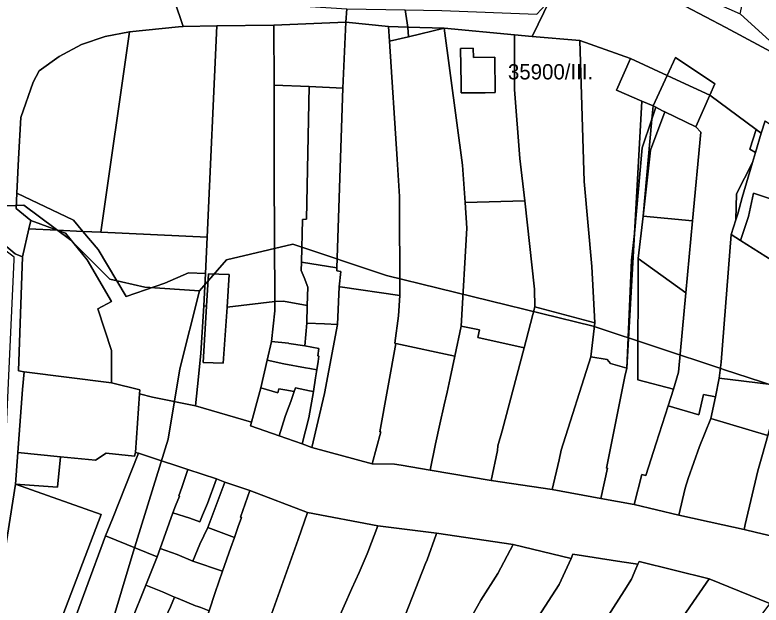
# Model space of a CAD drawing. Extents: x -545779 to -541342, y -1153413 to -1149956.
# Drawn here: x -544310.9 to -544066.7, y -1151258.7 to -1151065.6 of the extents above; entities that cross this region are included whole.
import ezdxf

# ---------------------------------------------------------------- set-up
doc = ezdxf.new("R2010")
doc.units = 0
for name, color, linetype in [('95590013', 7, 'Continuous'), ('95610013', 7, 'Continuous'), ('95630013', 7, 'Continuous'), ('95640013', 7, 'Continuous'), ('95660013', 7, 'Continuous')]:
    doc.layers.add(name, color=color, linetype=linetype)

msp = doc.modelspace()

# ---------------------------------------------------------------- linework, layer by layer
at = {"layer": '95590013'}
for points in [[(-544247.96, -1151138.3), (-544282.81, -1151136.71), (-544273.39, -1151071.2), (-544257.32, -1151069.5), (-544255.79, -1151069.46), (-544244.82, -1151069.16)], [(-544248.5, -1151150.2), (-544247.96, -1151138.3), (-544244.82, -1151069.16), (-544226.12, -1151068.98), (-544225.98, -1151088.64), (-544226, -1151117.83), (-544225.77, -1151159.43), (-544241.45, -1151161.21), (-544240.72, -1151150.55), (-544247.51, -1151150.33), (-544248.17, -1151160.9), (-544249.01, -1151160.82)], [(-544226.12, -1151068.98), (-544202.6, -1151068.01), (-544203.54, -1151089.61), (-544214.55, -1151089.05), (-544225.98, -1151088.64)], [(-544205.48, -1151148.34), (-544203.54, -1151089.61), (-544202.6, -1151068.01), (-544188.57, -1151069.43), (-544188.26, -1151074.21), (-544185.77, -1151112.81), (-544184.98, -1151125.02), (-544184.95, -1151157.48), (-544204.47, -1151154.62), (-544204.78, -1151154.62), (-544204.22, -1151149.61), (-544205.51, -1151149.34)], [(-544182.27, -1151069.63), (-544182.08, -1151072.75), (-544188.26, -1151074.21), (-544188.57, -1151069.43)], [(-544163.55, -1151126.98), (-544162.97, -1151135.38), (-544164.79, -1151167.47), (-544166.88, -1151177.25), (-544186.24, -1151173.11), (-544186.52, -1151173.06), (-544185.3, -1151164.08), (-544184.95, -1151157.48), (-544184.98, -1151125.02), (-544185.77, -1151112.81), (-544188.26, -1151074.21), (-544182.08, -1151072.75), (-544170.42, -1151070.01), (-544164.4, -1151114.73)], [(-544170.42, -1151070.01), (-544182.08, -1151072.75), (-544182.27, -1151069.63)], [(-544170.42, -1151070.01), (-544147.35, -1151072.15), (-544147.41, -1151089.99), (-544145.59, -1151112.58), (-544144.03, -1151126.47), (-544163.55, -1151126.98), (-544164.4, -1151114.73)], [(-544273.39, -1151071.2), (-544282.81, -1151136.71), (-544288.62, -1151136.45), (-544291.66, -1151132.82), (-544310.22, -1151123.99), (-544309.66, -1151112.71), (-544308.93, -1151099.17), (-544304.91, -1151087.65), (-544302.97, -1151083.97), (-544296.35, -1151079.23), (-544289.05, -1151075.26), (-544281.31, -1151072.64)], [(-544124.62, -1151120.16), (-544122.06, -1151147.94), (-544121.12, -1151166.34), (-544140.74, -1151161.13), (-544140.78, -1151155.39), (-544144.03, -1151126.47), (-544145.59, -1151112.58), (-544147.41, -1151089.99), (-544147.35, -1151072.15), (-544141.57, -1151072.66), (-544125.96, -1151074.03)], [(-544115.98, -1151179.69), (-544117.07, -1151178.42), (-544122.39, -1151177.54), (-544121.12, -1151166.34), (-544122.06, -1151147.94), (-544124.62, -1151120.16), (-544125.96, -1151074.03), (-544109.42, -1151079.88), (-544113.94, -1151090.25), (-544105.71, -1151093.81), (-544108.14, -1151137.18), (-544109.08, -1151145.89), (-544110.6, -1151181.19)], [(-544164.81, -1151091.15), (-544156.97, -1151091.07), (-544153.67, -1151091.03), (-544153.81, -1151079.45), (-544160.8, -1151079.58), (-544160.86, -1151076.55), (-544165.04, -1151076.58), (-544164.86, -1151088.21)], [(-544217.1, -1151146.57), (-544217.15, -1151149.2), (-544216.25, -1151151.53), (-544215.02, -1151154.75), (-544215.2, -1151160.66), (-544222.94, -1151159.3), (-544225.77, -1151159.43), (-544226, -1151117.83), (-544225.98, -1151088.64), (-544214.55, -1151089.05), (-544215.47, -1151132.41), (-544216.79, -1151132.59)], [(-544205.48, -1151148.34), (-544217.1, -1151146.57), (-544216.79, -1151132.59), (-544215.47, -1151132.41), (-544214.55, -1151089.05), (-544203.54, -1151089.61)], [(-544081.56, -1151190.58), (-544085.55, -1151189.84), (-544087.04, -1151196.46), (-544097.05, -1151193.5), (-544095.33, -1151188.07), (-544093.75, -1151182.48), (-544091.31, -1151156.59), (-544089.09, -1151133), (-544086.36, -1151104), (-544088.02, -1151102.27), (-544083.41, -1151091.9), (-544068.3, -1151103.16), (-544070.32, -1151109.55), (-544068.54, -1151110.59), (-544069.53, -1151113.95), (-544074.68, -1151124.16), (-544074.93, -1151132.72), (-544076.48, -1151137.47), (-544079.73, -1151179.27), (-544080.43, -1151184.43)], [(-544108.14, -1151137.18), (-544105.71, -1151093.81), (-544102.04, -1151095.4), (-544102.43, -1151099.74), (-544105.59, -1151109.08)], [(-544102.04, -1151095.4), (-544101.1, -1151095.81), (-544102.43, -1151099.74)], [(-544088.02, -1151102.27), (-544086.36, -1151104), (-544089.09, -1151133), (-544105.29, -1151131.49), (-544102.85, -1151109.89), (-544098.22, -1151097.35)], [(-544070.32, -1151109.55), (-544068.3, -1151103.16), (-544066.7, -1151104.36), (-544068.54, -1151110.59)], [(-544058.29, -1151131.2), (-544063.03, -1151145.95), (-544073.38, -1151139.43), (-544070.78, -1151131.61), (-544069.17, -1151123.91), (-544057.27, -1151127.84)], [(-544140.78, -1151155.39), (-544140.74, -1151161.13), (-544144.21, -1151174.55), (-544159.43, -1151171.18), (-544158.88, -1151168.64), (-544164.79, -1151167.47), (-544162.97, -1151135.38), (-544163.55, -1151126.98), (-544144.03, -1151126.47)], [(-544305.65, -1151132.88), (-544297.03, -1151136.06), (-544306.28, -1151135.64)], [(-544105.29, -1151131.49), (-544089.09, -1151133), (-544091.31, -1151156.59), (-544106.85, -1151145.29)], [(-544279.23, -1151159.42), (-544283.73, -1151161.78), (-544279.23, -1151175.47), (-544279.3, -1151185.98), (-544307.9, -1151182.39), (-544309.75, -1151182.11), (-544308.38, -1151144.78), (-544306.28, -1151135.64), (-544297.03, -1151136.06), (-544294.38, -1151137.04), (-544287.26, -1151145.75)], [(-544282.81, -1151136.71), (-544247.96, -1151138.3), (-544248.5, -1151150.2), (-544254.12, -1151150.03), (-544261.86, -1151153.44), (-544274.5, -1151157.79), (-544283.63, -1151142.4), (-544288.62, -1151136.45)], [(-544080.43, -1151184.43), (-544079.73, -1151179.27), (-544076.48, -1151137.47), (-544073.38, -1151139.43), (-544063.03, -1151145.95), (-544049.55, -1151155.05), (-544059.64, -1151186.38), (-544059.81, -1151186.98)], [(-544091.31, -1151156.59), (-544093.75, -1151182.48), (-544095.33, -1151188.07), (-544107.05, -1151184.97), (-544106.85, -1151145.29)], [(-544062.26, -1151195.54), (-544064.47, -1151203.23), (-544083.1, -1151197.62), (-544081.56, -1151190.58), (-544080.43, -1151184.43), (-544059.81, -1151186.98)], [(-544237.79, -1151232.99), (-544239.06, -1151236.62), (-544246.85, -1151233.7), (-544247.79, -1151233.34), (-544242.14, -1151218.52), (-544233.95, -1151221.19), (-544237.09, -1151229.98), (-544236.76, -1151230.1)], [(-544317.48, -1151261.56), (-544310.68, -1151219.21), (-544282.62, -1151229.03), (-544310.36, -1151301.85), (-544320.51, -1151297.8), (-544321.55, -1151281.26)], [(-544278.82, -1151279.15), (-544294.08, -1151270.98), (-544281.27, -1151236.08), (-544264.38, -1151242.96), (-544267.99, -1151252.2), (-544272.99, -1151264.39), (-544274.71, -1151268.41), (-544276.58, -1151273.29), (-544278.55, -1151278.44)]]:
    msp.add_lwpolyline(points, close=True, dxfattribs=at)
at = {"layer": '95610013'}
msp.add_lwpolyline([(-544046.53, -1150994.27), (-544062.75, -1151069.21), (-544063.79, -1151074.07), (-544073.49, -1151065.25), (-544056.62, -1150989.15)], close=True, dxfattribs=at)
at = {"layer": '95630013'}
msp.add_lwpolyline([(-544324.93, -1151277.46), (-544319.79, -1151256.39), (-544317.56, -1151243.24), (-544315.77, -1151230.23), (-544314.11, -1151209.76), (-544311.16, -1151145.77), (-544311.08, -1151144.88), (-544316.85, -1151140.73), (-544318.04, -1151141.16), (-544339.59, -1151133.35), (-544340.09, -1151132.86), (-544340.06, -1151129.45), (-544317.35, -1151134.76), (-544316.18, -1151137.4), (-544316.52, -1151139.06), (-544310.81, -1151143.81), (-544308.38, -1151144.78), (-544309.75, -1151182.11), (-544307.9, -1151182.39), (-544308.39, -1151188.2), (-544309.91, -1151208.84), (-544310.68, -1151219.21), (-544317.48, -1151261.56)], dxfattribs=at)
at = {"layer": '95640013'}
for points in [[(-544098.17, -1151059.13), (-544111.06, -1151046.56), (-544118.97, -1151035.55), (-544126.02, -1151025.74), (-544124.2, -1151022.22), (-544089.31, -1151058.21), (-544073.49, -1151065.25), (-544063.79, -1151074.07), (-544054.09, -1151079.29), (-544036.94, -1151082.63), (-544035.48, -1151082.92), (-544037.04, -1151089.82), (-544038.51, -1151089.36), (-544046.4, -1151086.9), (-544054.67, -1151082.43), (-544078.21, -1151069.72)], [(-544202.6, -1151068.01), (-544226.12, -1151068.98), (-544244.82, -1151069.16), (-544255.79, -1151069.46), (-544261.39, -1151052.79), (-544248.55, -1151060.53), (-544202.28, -1151063.65)], [(-544171.16, -1151064.15), (-544140.09, -1151065.42), (-544135.83, -1151060.82), (-544141.57, -1151072.66), (-544147.35, -1151072.15), (-544170.42, -1151070.01), (-544182.27, -1151069.63), (-544183.14, -1151063.96)], [(-544183.14, -1151063.96), (-544182.27, -1151069.63), (-544188.57, -1151069.43), (-544202.6, -1151068.01), (-544202.28, -1151063.65)], [(-544153.81, -1151079.45), (-544153.67, -1151091.03), (-544156.97, -1151091.07), (-544164.81, -1151091.15), (-544164.86, -1151088.21), (-544165.04, -1151076.58), (-544160.86, -1151076.55), (-544160.8, -1151079.58)], [(-544083.41, -1151091.9), (-544094.32, -1151086.86), (-544097.44, -1151085.42), (-544094.64, -1151079.56), (-544081.76, -1151088.18)], [(-544097.44, -1151085.42), (-544102.04, -1151095.4), (-544105.71, -1151093.81), (-544113.94, -1151090.25), (-544109.42, -1151079.88)], [(-544102.04, -1151095.4), (-544097.44, -1151085.42), (-544094.32, -1151086.86), (-544083.41, -1151091.9), (-544088.02, -1151102.27), (-544098.22, -1151097.35), (-544098.97, -1151096.95), (-544101.1, -1151095.81)], [(-544101.1, -1151095.81), (-544098.97, -1151096.95), (-544098.22, -1151097.35), (-544102.85, -1151109.89), (-544105.29, -1151131.49), (-544102.43, -1151099.74)], [(-544101, -1151205.74), (-544104.34, -1151216.33), (-544105.71, -1151216.02), (-544108.2, -1151225.81), (-544119.1, -1151223.83), (-544116.99, -1151213.95), (-544117.28, -1151213.89), (-544111.52, -1151184.97), (-544111.26, -1151183.88), (-544110.6, -1151181.19), (-544108.14, -1151137.18), (-544105.59, -1151109.08), (-544102.43, -1151099.74), (-544105.29, -1151131.49), (-544106.85, -1151145.29), (-544107.05, -1151184.97), (-544095.33, -1151188.07), (-544097.05, -1151193.5)], [(-544070.78, -1151131.61), (-544073.38, -1151139.43), (-544076.48, -1151137.47), (-544074.93, -1151132.72), (-544074.28, -1151130.71), (-544072.91, -1151125.4), (-544069.53, -1151113.95), (-544068.54, -1151110.59), (-544066.7, -1151104.36), (-544065.3, -1151100.32), (-544051.12, -1151109.86), (-544052.61, -1151114.16), (-544053.15, -1151115.97), (-544055.75, -1151123.2), (-544056.43, -1151125.18), (-544057.27, -1151127.84), (-544069.17, -1151123.91)], [(-544074.68, -1151124.16), (-544069.53, -1151113.95), (-544072.91, -1151125.4), (-544074.28, -1151130.71), (-544074.93, -1151132.72)], [(-544291.66, -1151132.82), (-544288.62, -1151136.45), (-544297.03, -1151136.06), (-544305.65, -1151132.88), (-544310.47, -1151128.98), (-544310.22, -1151123.99)], [(-544254.12, -1151150.03), (-544248.5, -1151150.2), (-544249.01, -1151160.82), (-544250.05, -1151176.24), (-544250.8, -1151184), (-544251.76, -1151193.56), (-544265.8, -1151190.64), (-544270.06, -1151189.65), (-544269.95, -1151188.34), (-544279.3, -1151185.98), (-544279.23, -1151175.47), (-544283.73, -1151161.78), (-544279.23, -1151159.42), (-544287.26, -1151145.75), (-544294.38, -1151137.04), (-544297.03, -1151136.06), (-544288.62, -1151136.45), (-544283.63, -1151142.4), (-544274.5, -1151157.79), (-544261.86, -1151153.44)], [(-544108.14, -1151137.18), (-544110.6, -1151181.19), (-544109.08, -1151145.89)], [(-544216.25, -1151151.53), (-544217.15, -1151149.2), (-544217.1, -1151146.57), (-544205.48, -1151148.34), (-544205.51, -1151149.34), (-544204.22, -1151149.61), (-544204.78, -1151154.62), (-544205.3, -1151166.89), (-544209.55, -1151166.69), (-544215.38, -1151166.45), (-544215.2, -1151160.66), (-544215.02, -1151154.75)], [(-544241.45, -1151161.21), (-544242.72, -1151179.58), (-544249.31, -1151179.3), (-544248.17, -1151160.9), (-544247.51, -1151150.33), (-544240.72, -1151150.55)], [(-544191.4, -1151202), (-544191.11, -1151202.08), (-544194, -1151212.55), (-544213.68, -1151207.15), (-544209.56, -1151189.49), (-544205.3, -1151166.89), (-544204.78, -1151154.62), (-544204.47, -1151154.62), (-544184.95, -1151157.48), (-544185.3, -1151164.08), (-544186.52, -1151173.06), (-544186.24, -1151173.11)], [(-544250.8, -1151184), (-544250.05, -1151176.24), (-544249.01, -1151160.82), (-544248.17, -1151160.9), (-544249.31, -1151179.3), (-544242.72, -1151179.58), (-544241.45, -1151161.21), (-544225.77, -1151159.43), (-544225.79, -1151162.42), (-544226.88, -1151172.47), (-544228.32, -1151178.62), (-544230.44, -1151187.69), (-544231, -1151190.07), (-544233.48, -1151198.92), (-544251.76, -1151193.56)], [(-544221.29, -1151173), (-544226.88, -1151172.47), (-544225.79, -1151162.42), (-544225.77, -1151159.43), (-544222.94, -1151159.3), (-544215.2, -1151160.66), (-544215.38, -1151166.45), (-544216.05, -1151173.94), (-544221.22, -1151173.17)], [(-544121.12, -1151166.34), (-544122.39, -1151177.54), (-544132.05, -1151208.01), (-544132.8, -1151211.22), (-544135.07, -1151220.92), (-544155.03, -1151217.91), (-544152.98, -1151208.13), (-544152.82, -1151206.59), (-544151.46, -1151201.76), (-544144.21, -1151174.55), (-544140.74, -1151161.13)], [(-544205.3, -1151166.89), (-544209.56, -1151189.49), (-544213.68, -1151207.15), (-544216.85, -1151206), (-544214.73, -1151197.42), (-544213.19, -1151188.83), (-544212.5, -1151184.4), (-544212.1, -1151181.8), (-544211.68, -1151179.03), (-544211.4, -1151177.24), (-544211.75, -1151177.19), (-544211.37, -1151174.78), (-544216.05, -1151173.94), (-544215.38, -1151166.45), (-544209.55, -1151166.69)], [(-544164.79, -1151167.47), (-544158.88, -1151168.64), (-544159.43, -1151171.18), (-544144.21, -1151174.55), (-544151.46, -1151201.76), (-544152.82, -1151206.59), (-544152.98, -1151208.13), (-544155.03, -1151217.91), (-544174.98, -1151214.61), (-544173.26, -1151205.98), (-544171.77, -1151199.57), (-544170.35, -1151193.2), (-544169.43, -1151189.08), (-544168.41, -1151184.43), (-544166.88, -1151177.25)], [(-544215.8, -1151181.1), (-544222.82, -1151179.81), (-544228.32, -1151178.62), (-544226.88, -1151172.47), (-544221.29, -1151173), (-544221.22, -1151173.17), (-544216.05, -1151173.94), (-544211.37, -1151174.78), (-544211.75, -1151177.19), (-544211.4, -1151177.24), (-544211.68, -1151179.03), (-544212.1, -1151181.8), (-544214.39, -1151181.28)], [(-544166.88, -1151177.25), (-544168.41, -1151184.43), (-544169.43, -1151189.08), (-544170.35, -1151193.2), (-544171.77, -1151199.57), (-544173.26, -1151205.98), (-544174.98, -1151214.61), (-544184.48, -1151212.99), (-544186.63, -1151212.66), (-544194, -1151212.55), (-544191.11, -1151202.08), (-544191.4, -1151202), (-544186.24, -1151173.11)], [(-544222.57, -1151188.29), (-544224.56, -1151187.95), (-544224.84, -1151189.3), (-544230.44, -1151187.69), (-544228.32, -1151178.62), (-544222.82, -1151179.81), (-544215.8, -1151181.1), (-544214.39, -1151181.28), (-544212.1, -1151181.8), (-544212.5, -1151184.4), (-544213.19, -1151188.83), (-544214.44, -1151188.57), (-544219.02, -1151187.63), (-544219.44, -1151188.8)], [(-544117.28, -1151213.89), (-544116.99, -1151213.95), (-544119.1, -1151223.83), (-544135.07, -1151220.92), (-544132.8, -1151211.22), (-544132.05, -1151208.01), (-544122.39, -1151177.54), (-544117.07, -1151178.42), (-544115.98, -1151179.69), (-544110.6, -1151181.19), (-544111.26, -1151183.88), (-544111.52, -1151184.97)], [(-544281.03, -1151208.99), (-544284.56, -1151211.3), (-544295.98, -1151210.19), (-544309.91, -1151208.84), (-544308.39, -1151188.2), (-544307.9, -1151182.39), (-544279.3, -1151185.98), (-544269.95, -1151188.34), (-544270.06, -1151189.65), (-544271.45, -1151208.83), (-544271.73, -1151209.97)], [(-544219.44, -1151188.8), (-544220.6, -1151192.06), (-544221.7, -1151194.95), (-544222.48, -1151197.02), (-544224.38, -1151203.33), (-544233.8, -1151200.03), (-544233.48, -1151198.92), (-544231, -1151190.07), (-544230.44, -1151187.69), (-544224.84, -1151189.3), (-544224.56, -1151187.95), (-544222.57, -1151188.29)], [(-544214.73, -1151197.42), (-544216.85, -1151206), (-544224.38, -1151203.33), (-544222.48, -1151197.02), (-544221.7, -1151194.95), (-544220.6, -1151192.06), (-544219.44, -1151188.8), (-544219.02, -1151187.63), (-544214.44, -1151188.57), (-544213.19, -1151188.83)], [(-544085.55, -1151189.84), (-544081.56, -1151190.58), (-544083.1, -1151197.62), (-544086.81, -1151206.81), (-544090.52, -1151217.32), (-544091.51, -1151220.48), (-544093.63, -1151229.29), (-544108.2, -1151225.81), (-544105.71, -1151216.02), (-544104.34, -1151216.33), (-544101, -1151205.74), (-544097.05, -1151193.5), (-544087.04, -1151196.46)], [(-544071.92, -1151232.35), (-544067.77, -1151214.77), (-544066.26, -1151209.48), (-544064.47, -1151203.23), (-544062.26, -1151195.54), (-544040.78, -1151201.75), (-544050.68, -1151230.02), (-544053.24, -1151238.41), (-544061.61, -1151236.53), (-544068.15, -1151235), (-544072.2, -1151234)], [(-544091.51, -1151220.48), (-544090.52, -1151217.32), (-544086.81, -1151206.81), (-544083.1, -1151197.62), (-544064.47, -1151203.23), (-544066.26, -1151209.48), (-544067.77, -1151214.77), (-544071.92, -1151232.35), (-544072.2, -1151234), (-544079.19, -1151232.44), (-544093.63, -1151229.29)], [(-544270.44, -1151209), (-544278.93, -1151230.53), (-544281.27, -1151236.08), (-544294.08, -1151270.98), (-544300.12, -1151286.59), (-544301.19, -1151289.35), (-544306.65, -1151303.34), (-544310.36, -1151301.85), (-544282.62, -1151229.03), (-544310.68, -1151219.21), (-544296.94, -1151220.15), (-544295.98, -1151210.19), (-544284.56, -1151211.3), (-544281.03, -1151208.99), (-544271.73, -1151209.97), (-544271.45, -1151208.83)], [(-544309.91, -1151208.84), (-544295.98, -1151210.19), (-544296.94, -1151220.15), (-544310.68, -1151219.21)], [(-544259.16, -1151228.52), (-544263.32, -1151240.24), (-544264.38, -1151242.96), (-544281.27, -1151236.08), (-544278.93, -1151230.53), (-544270.44, -1151209), (-544266.53, -1151210.37), (-544254.27, -1151214.4), (-544256.26, -1151220.27), (-544257.2, -1151222.99), (-544257.06, -1151223.04), (-544258.28, -1151226.22)], [(-544256.26, -1151220.27), (-544254.27, -1151214.4), (-544244.94, -1151217.45), (-544247.9, -1151225.5), (-544249.46, -1151229.26), (-544250.34, -1151231.48), (-544253.65, -1151230.26), (-544259.16, -1151228.52), (-544258.28, -1151226.22), (-544257.06, -1151223.04), (-544257.2, -1151222.99)], [(-544253.65, -1151230.26), (-544250.34, -1151231.48), (-544249.46, -1151229.26), (-544247.9, -1151225.5), (-544244.94, -1151217.45), (-544242.14, -1151218.52), (-544247.79, -1151233.34), (-544250.41, -1151238.83), (-544252.61, -1151244.35), (-544257.78, -1151242.16), (-544263.32, -1151240.24), (-544259.16, -1151228.52)], [(-544233.95, -1151221.19), (-544215.15, -1151228.39), (-544218.13, -1151237.23), (-544232.38, -1151276.98), (-544249.96, -1151267.81), (-544247.29, -1151260.6), (-544245.37, -1151254.55), (-544242.89, -1151247.57), (-544240.19, -1151239.83), (-544239.06, -1151236.62), (-544237.79, -1151232.99), (-544236.76, -1151230.1), (-544237.09, -1151229.98)], [(-544192.11, -1151232.82), (-544195.39, -1151241.43), (-544195.59, -1151241.96), (-544198.2, -1151248.07), (-544200.63, -1151253.34), (-544205.59, -1151264.63), (-544210.83, -1151278.67), (-544220.91, -1151275.43), (-544237.18, -1151318.45), (-544229.11, -1151321.68), (-544231.01, -1151326.43), (-544235.8, -1151335.76), (-544258.81, -1151326.24), (-544253.8, -1151318.93), (-544252.04, -1151317.08), (-544245.59, -1151307.77), (-544232.38, -1151276.98), (-544218.13, -1151237.23), (-544215.15, -1151228.39)], [(-544247.79, -1151233.34), (-544246.85, -1151233.7), (-544239.06, -1151236.62), (-544240.19, -1151239.83), (-544242.89, -1151247.57), (-544252.61, -1151244.35), (-544250.41, -1151238.83)], [(-544195.59, -1151241.96), (-544195.39, -1151241.43), (-544192.11, -1151232.82), (-544172.85, -1151235.23), (-544173, -1151235.65), (-544175.98, -1151243.88), (-544176.46, -1151245.09), (-544186.43, -1151270.42), (-544205.59, -1151264.63), (-544200.63, -1151253.34), (-544198.2, -1151248.07)], [(-544183.39, -1151291.3), (-544184.77, -1151291.38), (-544198.77, -1151312.95), (-544197.8, -1151315.18), (-544187.84, -1151320.21), (-544192.28, -1151332.61), (-544200.34, -1151331.28), (-544201.39, -1151334.72), (-544214.06, -1151330.84), (-544206.77, -1151311.61), (-544202.88, -1151302.79), (-544188.28, -1151275.15), (-544186.43, -1151270.42), (-544176.46, -1151245.09), (-544175.98, -1151243.88), (-544173, -1151235.65), (-544172.85, -1151235.23), (-544147.79, -1151238.88), (-544152.83, -1151248.37), (-544158.38, -1151257.07), (-544170.37, -1151278.58), (-544172.24, -1151282.28), (-544178.37, -1151293.74)], [(-544267.99, -1151252.2), (-544264.38, -1151242.96), (-544263.32, -1151240.24), (-544257.78, -1151242.16), (-544252.61, -1151244.35), (-544242.89, -1151247.57), (-544245.37, -1151254.55), (-544247.29, -1151260.6), (-544250.08, -1151259.56), (-544251.02, -1151259.2), (-544251.79, -1151258.91), (-544257.42, -1151256.53), (-544258.6, -1151256.09), (-544262.6, -1151254.38)], [(-544147.21, -1151277.05), (-544150.83, -1151283.9), (-544151.91, -1151283.38), (-544152.35, -1151284.62), (-544160.03, -1151281.09), (-544168.54, -1151300.36), (-544161.33, -1151303.12), (-544165.89, -1151311.67), (-544169.6, -1151320.7), (-544176.15, -1151337.85), (-544192.54, -1151334.15), (-544192.28, -1151332.61), (-544187.84, -1151320.21), (-544178.37, -1151293.74), (-544172.24, -1151282.28), (-544170.37, -1151278.58), (-544158.38, -1151257.07), (-544152.83, -1151248.37), (-544147.79, -1151238.88), (-544128.88, -1151243.44), (-544132.71, -1151251.93), (-544139.7, -1151262.81)], [(-544107.68, -1151246.89), (-544109.11, -1151250.22), (-544111.52, -1151254.1), (-544116.7, -1151262.24), (-544124.29, -1151274.19), (-544127.38, -1151280.22), (-544128.12, -1151280.34), (-544131.33, -1151285.21), (-544142.33, -1151279.55), (-544147.21, -1151277.05), (-544139.7, -1151262.81), (-544132.71, -1151251.93), (-544128.88, -1151243.44), (-544128.27, -1151242.08), (-544112.23, -1151244.54), (-544107.01, -1151245.34)], [(-544128.12, -1151280.34), (-544127.38, -1151280.22), (-544124.29, -1151274.19), (-544116.7, -1151262.24), (-544111.52, -1151254.1), (-544109.11, -1151250.22), (-544107.68, -1151246.89), (-544107.01, -1151245.34), (-544106.61, -1151244.41), (-544083.61, -1151250.16), (-544087.77, -1151256.1), (-544091.19, -1151261.01), (-544098.76, -1151271.98), (-544108.91, -1151286.71), (-544111.18, -1151289.96), (-544115.25, -1151295.79), (-544133.56, -1151288.61), (-544131.33, -1151285.21)], [(-544080.63, -1151280.41), (-544084.37, -1151284.88), (-544090.43, -1151293.42), (-544090.97, -1151293.11), (-544091.38, -1151292.91), (-544102.57, -1151287.39), (-544104.23, -1151289.8), (-544108.91, -1151286.71), (-544098.76, -1151271.98), (-544091.19, -1151261.01), (-544087.77, -1151256.1), (-544083.61, -1151250.16), (-544063.84, -1151258.25)], [(-544267.99, -1151252.2), (-544262.6, -1151254.38), (-544258.6, -1151256.09), (-544259.95, -1151259.34), (-544261.6, -1151262.8), (-544265.41, -1151270.38), (-544272.62, -1151276.01), (-544276.58, -1151273.29), (-544274.71, -1151268.41), (-544272.99, -1151264.39)], [(-544259.95, -1151259.34), (-544258.6, -1151256.09), (-544257.42, -1151256.53), (-544251.79, -1151258.91), (-544251.02, -1151259.2), (-544250.08, -1151259.56), (-544247.29, -1151260.6), (-544249.96, -1151267.81), (-544261.6, -1151262.8)]]:
    msp.add_lwpolyline(points, close=True, dxfattribs=at)
for points in [[(-544261.39, -1151052.79), (-544255.79, -1151069.46), (-544257.32, -1151069.5), (-544273.39, -1151071.2), (-544281.31, -1151072.64), (-544289.05, -1151075.26), (-544296.35, -1151079.23), (-544302.97, -1151083.97), (-544304.91, -1151087.65), (-544308.93, -1151099.17), (-544309.66, -1151112.71), (-544310.22, -1151123.99), (-544310.47, -1151128.98), (-544305.65, -1151132.88), (-544306.28, -1151135.64), (-544308.38, -1151144.78), (-544310.81, -1151143.81), (-544316.52, -1151139.06)], [(-544098.17, -1151059.13), (-544078.21, -1151069.72), (-544054.67, -1151082.43)], [(-544065.3, -1151100.32), (-544066.7, -1151104.36), (-544068.3, -1151103.16), (-544083.41, -1151091.9), (-544081.76, -1151088.18), (-544094.64, -1151079.56), (-544097.44, -1151085.42), (-544109.42, -1151079.88), (-544125.96, -1151074.03), (-544141.57, -1151072.66), (-544135.83, -1151060.82)], [(-544063.84, -1151258.25), (-544083.61, -1151250.16), (-544106.61, -1151244.41), (-544107.01, -1151245.34), (-544112.23, -1151244.54), (-544128.27, -1151242.08), (-544128.88, -1151243.44), (-544147.79, -1151238.88), (-544172.85, -1151235.23), (-544192.11, -1151232.82), (-544215.15, -1151228.39), (-544233.95, -1151221.19), (-544242.14, -1151218.52), (-544244.94, -1151217.45), (-544254.27, -1151214.4), (-544266.53, -1151210.37), (-544270.44, -1151209), (-544271.45, -1151208.83), (-544270.06, -1151189.65), (-544265.8, -1151190.64), (-544251.76, -1151193.56), (-544233.48, -1151198.92), (-544233.8, -1151200.03), (-544224.38, -1151203.33), (-544216.85, -1151206), (-544213.68, -1151207.15), (-544194, -1151212.55), (-544186.63, -1151212.66), (-544184.48, -1151212.99), (-544174.98, -1151214.61), (-544155.03, -1151217.91), (-544135.07, -1151220.92), (-544119.1, -1151223.83), (-544108.2, -1151225.81), (-544093.63, -1151229.29), (-544079.19, -1151232.44), (-544072.2, -1151234), (-544068.15, -1151235), (-544061.61, -1151236.53)]]:
    msp.add_lwpolyline(points, dxfattribs=at)
at = {"layer": '95660013'}
for points in [[(-544032.324, -1151196.783), (-544079.025, -1151181.636), (-544079.535, -1151181.471), (-544121.642, -1151167.436), (-544189.268, -1151150.848), (-544219.89, -1151140.64), (-544241.583, -1151145.744), (-544250.513, -1151155.952), (-544268.377, -1151154.676), (-544279.862, -1151152.124), (-544292.621, -1151139.364), (-544307.932, -1151127.881), (-544342.384, -1151129.157), (-544350.717, -1151164.986), (-544359.504, -1151162.541), (-544395.215, -1151149.788), (-544409.669, -1151143.411), (-544431.774, -1151136.184), (-544434.325, -1151134.484), (-544444.103, -1151131.083), (-544458.132, -1151124.706), (-544483.213, -1151114.504), (-544489.59, -1151112.378)], [(-544336.004, -1151291.204), (-544327.072, -1151247.821), (-544355.143, -1151236.338), (-544355.143, -1151215.922), (-544350.717, -1151164.986), (-544342.384, -1151129.157), (-544307.932, -1151127.881), (-544292.621, -1151139.364), (-544279.862, -1151152.124), (-544268.377, -1151154.676), (-544250.513, -1151155.952), (-544256.893, -1151181.471), (-544260.721, -1151204.439), (-544272.206, -1151241.442), (-544283.689, -1151279.721)], [(-544283.689, -1151279.721), (-544272.206, -1151241.442), (-544260.721, -1151204.439), (-544256.893, -1151181.471), (-544250.513, -1151155.952), (-544241.583, -1151145.744), (-544219.89, -1151140.64), (-544189.268, -1151150.848), (-544121.642, -1151167.436), (-544079.535, -1151181.471), (-544079.025, -1151181.636), (-544032.324, -1151196.783)]]:
    msp.add_lwpolyline(points, dxfattribs=at)

# ---------------------------------------------------------------- texts
msp.add_text('35900/III.', height=5, rotation=0, dxfattribs=at).set_placement((-544149.515, -1151086.731))

doc.saveas('drawing.dxf')
